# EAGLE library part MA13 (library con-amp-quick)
AMP QUICK CONNECTOR
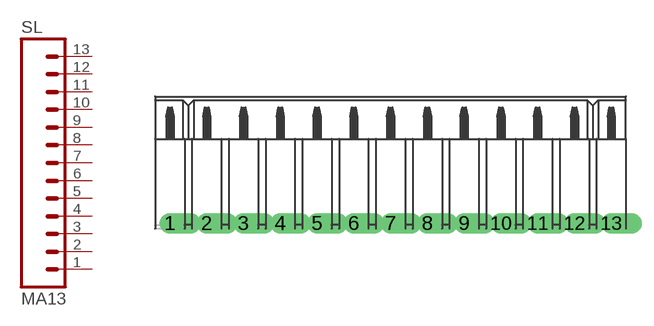
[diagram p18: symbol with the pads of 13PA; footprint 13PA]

Designator prefix SL

## MA13  [13PA]
1  1  pas
2  2  pas
3  3  pas
4  4  pas
5  5  pas
6  6  pas
7  7  pas
8  8  pas
9  9  pas
10  10  pas
11  11  pas
12  12  pas
13  13  pas

## Footprint 13PA (pad centres in mm)
AMP QUICK CONNECTOR
drill 0.914 offset: 1 -15.24,0; 2 -12.7,0; 3 -10.16,0; 4 -7.62,0; 5 -5.08,0; 6 -2.54,0; 7 0,0; 8 2.54,0; 9 5.08,0; 10 7.62,0; 11 10.16,0; 12 12.7,0; 13 15.24,0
